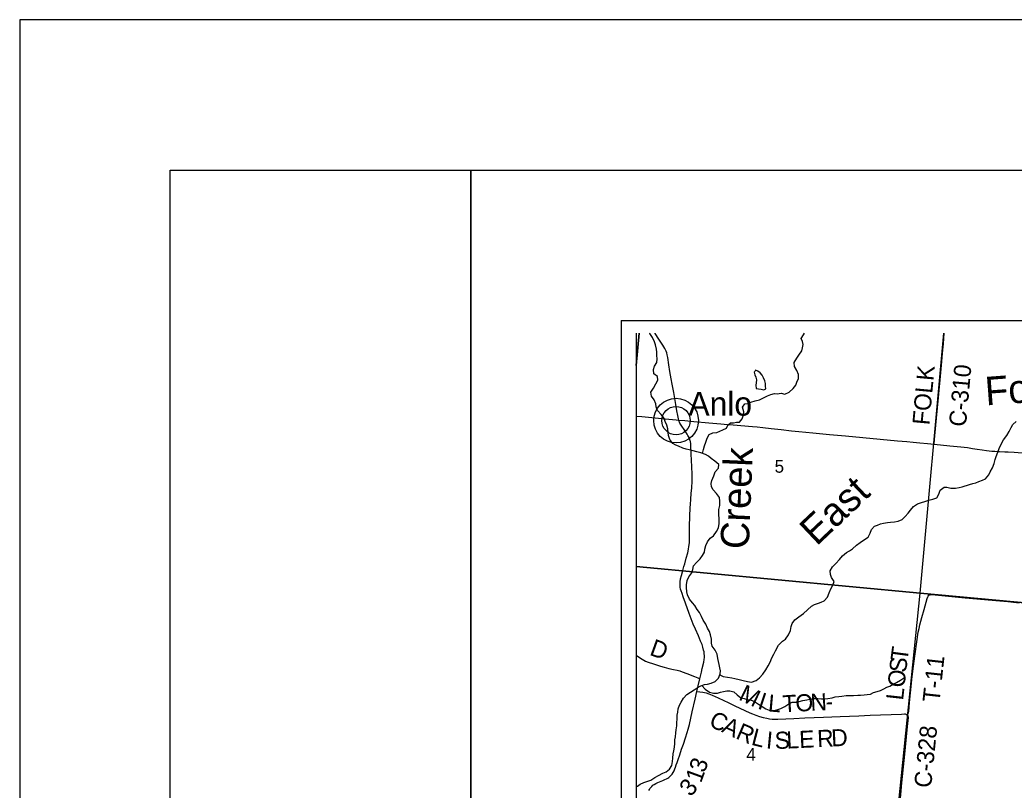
# Model space of a CAD drawing. Extents: x 0 to 34, y 0 to 22.
# Drawn here: x 0 to 3.306, y 19.439 to 22 of the extents above; entities that cross this region are included whole.
import ezdxf

# ---------------------------------------------------------------- set-up
doc = ezdxf.new("R2010")
doc.units = 0
for name, color, linetype in [('GM_X_Corporation', 7, 'Continuous'), ('GM_X_County_Road', 7, 'Continuous'), ('GM_X_County_Road_Text', 7, 'Continuous'), ('GM_X_Minor_Lake', 7, 'Continuous'), ('GM_X_Minor_River', 7, 'Continuous'), ('GM_X_Minor_River_Text', 7, 'Continuous'), ('GM_X_Section_Text', 7, 'Continuous'), ('GM_X_Township_Road', 7, 'Continuous'), ('GM_X_Township_Road_Text', 7, 'Continuous'), ('GM_X_Unincorporated', 7, 'Continuous'), ('GM_X_Unincorporated_Location', 7, 'Continuous'), ('GM_X_Unincorporated_Text', 7, 'Continuous'), ('SH_Border', 7, 'Continuous'), ('SH_Cut_Line', 7, 'Continuous'), ('SH_Data', 7, 'Continuous')]:
    doc.layers.add(name, color=color, linetype=linetype)

msp = doc.modelspace()

# ---------------------------------------------------------------- linework, layer by layer
at = {"layer": 'GM_X_Corporation'}
msp.add_line((2.0494, 20.9578), (2.0494, 17.7739), dxfattribs=at)
for points in [[(2.0494, 20.9578), (2.0494, 20.8508), (2.0598, 20.9578)], [(2.0598, 20.9578), (2.0494, 20.8508), (2.0494, 20.1825), (2.9941, 20.0934), (3.0731, 20.9578)], [(4.0205, 20.9578), (3.9531, 20.0055), (2.9941, 20.0934), (3.0731, 20.9578)]]:
    msp.add_lwpolyline(points, dxfattribs=at)
for points in [[(2.0494, 20.1825), (2.0494, 19.1379), (2.8892, 19.065), (2.9941, 20.0934)], [(2.9941, 20.0934), (3.9531, 20.0055), (3.9103, 18.9545), (2.8892, 19.065)]]:
    msp.add_lwpolyline(points, close=True, dxfattribs=at)
at = {"layer": 'GM_X_County_Road'}
for points in [[(2.1912, 20.6692), (2.1903, 20.6731), (2.188, 20.6847), (2.1853, 20.7), (2.1817, 20.7214), (2.1745, 20.7611), (2.1692, 20.7885), (2.1661, 20.8069), (2.162, 20.8312), (2.1586, 20.8528), (2.1549, 20.8769), (2.154, 20.8816), (2.1528, 20.8866), (2.1511, 20.8926), (2.149, 20.8985), (2.145, 20.9067), (2.138, 20.9178), (2.1252, 20.9384), (2.1132, 20.957), (2.1127, 20.9578)], [(3.0411, 20.589), (3.0422, 20.6048), (3.0486, 20.6759), (3.055, 20.7438), (3.0572, 20.7686), (3.0603, 20.8025), (3.0659, 20.8644), (3.0684, 20.8922), (3.0713, 20.9231), (3.0743, 20.9578)], [(2.0494, 20.6826), (2.0683, 20.6808), (2.1459, 20.6735), (2.183, 20.67), (2.1912, 20.6692)], [(2.2617, 19.8092), (2.2669, 19.8311), (2.2694, 19.843), (2.2741, 19.8643), (2.2759, 19.8735), (2.2765, 19.8797), (2.2766, 19.886), (2.2762, 19.8923), (2.2753, 19.8985), (2.274, 19.9046), (2.2715, 19.9137), (2.2685, 19.9225), (2.264, 19.9341), (2.2567, 19.9513), (2.2464, 19.9739), (2.239, 19.991), (2.2289, 20.0169), (2.2255, 20.0255), (2.2135, 20.0599), (2.2059, 20.0809), (2.2022, 20.0923), (2.1991, 20.1011), (2.1974, 20.1073), (2.1964, 20.1134), (2.1957, 20.1196), (2.1956, 20.1254), (2.196, 20.1317), (2.1972, 20.141), (2.1999, 20.1529), (2.2032, 20.1649), (2.2056, 20.1733), (2.2083, 20.1825), (2.2111, 20.1914), (2.2162, 20.2096), (2.2211, 20.2273), (2.2238, 20.2395), (2.2252, 20.2487), (2.2264, 20.2612), (2.2269, 20.2736), (2.227, 20.2923), (2.2271, 20.3233), (2.2275, 20.3419), (2.2278, 20.3481), (2.2282, 20.3573), (2.2286, 20.3696), (2.2291, 20.3789), (2.2299, 20.3882), (2.2313, 20.4065), (2.2329, 20.4253), (2.2344, 20.4439), (2.2357, 20.4656), (2.2361, 20.478), (2.2359, 20.4905), (2.2349, 20.5122), (2.2335, 20.5368), (2.2326, 20.5553), (2.2315, 20.5832), (2.2314, 20.5863), (2.2311, 20.5892), (2.2308, 20.5919), (2.2303, 20.5948), (2.2297, 20.5977), (2.2291, 20.6005), (2.2283, 20.6037), (2.2272, 20.6068), (2.2253, 20.6112), (2.2219, 20.6175), (2.2191, 20.6226), (2.2137, 20.631), (2.1967, 20.6561), (2.195, 20.6591), (2.1936, 20.6618), (2.1927, 20.664), (2.1916, 20.6672), (2.1912, 20.6692)], [(2.1912, 20.6692), (2.2109, 20.6673), (2.2418, 20.6644), (2.2913, 20.66), (2.3315, 20.6563), (2.3532, 20.6545), (2.3717, 20.6531), (2.4365, 20.6476), (2.452, 20.6462), (2.4705, 20.6443), (2.4982, 20.641), (2.5322, 20.6376), (2.5662, 20.634), (2.5909, 20.6315), (2.6373, 20.627), (2.693, 20.6216), (2.7455, 20.6167), (2.9187, 20.6006), (2.9497, 20.5977), (2.9713, 20.5957), (2.9929, 20.5937), (3.018, 20.5914), (3.0411, 20.589)], [(3.0411, 20.589), (3.0931, 20.5837), (3.1289, 20.5802), (3.1511, 20.5777), (3.1686, 20.5752), (3.1831, 20.5729), (3.2001, 20.57), (3.2141, 20.5682), (3.2323, 20.5663), (3.2418, 20.5655), (3.2515, 20.5649), (3.2578, 20.5646), (3.2761, 20.5637), (3.2871, 20.5632), (3.3064, 20.5623), (3.3328, 20.5606)], [(2.0494, 19.8876), (2.057, 19.8822), (2.07, 19.8737), (2.0754, 19.8707), (2.0811, 19.868), (2.0899, 19.8647), (2.1075, 19.8586), (2.131, 19.8507), (2.143, 19.8472), (2.1581, 19.8435), (2.1733, 19.8403), (2.1854, 19.8377), (2.1943, 19.8352), (2.203, 19.8322), (2.2175, 19.8267), (2.2433, 19.8161), (2.2549, 19.8117), (2.2617, 19.8092)], [(2.2517, 19.7671), (2.256, 19.7857), (2.2617, 19.8092)], [(2.0921, 19.4378), (2.0936, 19.441), (2.0952, 19.4436), (2.0969, 19.4462), (2.0989, 19.4486), (2.1011, 19.4509), (2.1054, 19.4547), (2.1089, 19.457), (2.1154, 19.4607), (2.1213, 19.4637), (2.1386, 19.4709), (2.1444, 19.4736), (2.1502, 19.4763), (2.1547, 19.4788), (2.1579, 19.4811), (2.1623, 19.4846), (2.1659, 19.4881), (2.1692, 19.4919), (2.1727, 19.4973), (2.1755, 19.503), (2.1782, 19.5096), (2.1803, 19.5153), (2.183, 19.5226), (2.1854, 19.5301), (2.1888, 19.54), (2.1946, 19.5565), (2.2007, 19.5744), (2.2066, 19.5918), (2.2136, 19.6122), (2.2194, 19.6298), (2.2229, 19.6416), (2.2267, 19.6566), (2.2362, 19.6989), (2.246, 19.7412), (2.2517, 19.7671)], [(2.2517, 19.7671), (2.2618, 19.7659), (2.2709, 19.7646), (2.2769, 19.7633), (2.2828, 19.7617), (2.2915, 19.7587), (2.3028, 19.754), (2.3225, 19.7451), (2.3416, 19.7362), (2.3555, 19.7298), (2.3779, 19.7192), (2.411, 19.7033), (2.4277, 19.6956), (2.4362, 19.692), (2.4479, 19.6876), (2.4597, 19.6838), (2.4717, 19.6805), (2.4838, 19.6776), (2.4929, 19.6758), (2.5022, 19.6746), (2.5116, 19.6742), (2.5209, 19.6744), (2.5735, 19.6769), (2.6107, 19.6788), (2.6726, 19.6815), (2.7283, 19.6837), (2.7903, 19.6859), (2.8275, 19.6875), (2.9322, 19.6918), (2.9424, 19.6921), (2.9446, 19.6919), (2.9463, 19.6915), (2.948, 19.6907), (2.9494, 19.6899), (2.9516, 19.6883)], [(2.9516, 19.6883), (2.9528, 19.6866), (2.9535, 19.6849), (2.954, 19.6821), (2.9541, 19.6791), (2.9534, 19.6699), (2.9499, 19.6389), (2.9418, 19.5586), (2.9324, 19.4628), (2.9284, 19.4226), (2.9243, 19.3827), (2.9197, 19.334), (2.9161, 19.3), (2.9134, 19.2724), (2.9106, 19.2475)]]:
    msp.add_lwpolyline(points, dxfattribs=at)
at = {"layer": 'GM_X_Minor_Lake'}
for points in [[(2.4437, 20.8312), (2.442, 20.8289), (2.4445, 20.8198), (2.4479, 20.8114), (2.4493, 20.8026), (2.4488, 20.7935), (2.4475, 20.7855), (2.4489, 20.7741)], [(2.4489, 20.7741), (2.4569, 20.7733), (2.4648, 20.7717), (2.4739, 20.7693), (2.4804, 20.773), (2.4798, 20.7821), (2.4799, 20.7909), (2.4773, 20.7996), (2.4733, 20.8092), (2.4685, 20.8184), (2.4621, 20.8268), (2.4546, 20.8322), (2.4466, 20.835), (2.4437, 20.8312)]]:
    msp.add_lwpolyline(points, dxfattribs=at)
at = {"layer": 'GM_X_Minor_River'}
for points in [[(2.227, 20.0741), (2.2207, 20.0886), (2.2181, 20.0981), (2.2164, 20.1122), (2.2165, 20.1217), (2.2186, 20.1354), (2.2252, 20.1475), (2.2349, 20.1614), (2.2377, 20.172), (2.2405, 20.1849), (2.2502, 20.1958), (2.2625, 20.2082), (2.2706, 20.2191), (2.2768, 20.2301), (2.2784, 20.2403), (2.2812, 20.2517), (2.2867, 20.2645), (2.2952, 20.2762), (2.3067, 20.2848), (2.3172, 20.2988), (2.3238, 20.3112), (2.3259, 20.3249), (2.3256, 20.3344), (2.3244, 20.3618), (2.3249, 20.3716), (2.3274, 20.3849), (2.3279, 20.3997), (2.3262, 20.4119), (2.3172, 20.4253), (2.3052, 20.4376), (2.3001, 20.4472), (2.2994, 20.4586), (2.3015, 20.4681), (2.3077, 20.4839), (2.3128, 20.4968), (2.3229, 20.5092), (2.3242, 20.5218), (2.3114, 20.5326), (2.2993, 20.5414), (2.2896, 20.5495), (2.2798, 20.5542), (2.265, 20.5605), (2.251, 20.5633), (2.2389, 20.5669), (2.226, 20.5701), (2.2158, 20.5725), (2.2044, 20.576), (2.1908, 20.5823), (2.181, 20.5858), (2.1712, 20.5916), (2.1615, 20.6043), (2.1567, 20.6176), (2.1565, 20.6279), (2.1547, 20.6397), (2.1515, 20.6523), (2.1463, 20.6649), (2.1415, 20.6771), (2.1322, 20.6879), (2.1202, 20.7009), (2.1162, 20.7135), (2.1148, 20.723), (2.1096, 20.736), (2.1006, 20.7483), (2.0978, 20.7616), (2.1071, 20.7752), (2.1148, 20.7892), (2.1218, 20.802), (2.1205, 20.8142), (2.1084, 20.8235), (2.1071, 20.8379), (2.111, 20.8481), (2.1188, 20.8602), (2.1197, 20.8727), (2.1179, 20.8841), (2.1184, 20.8948), (2.1171, 20.9047), (2.1142, 20.9192), (2.1105, 20.9291), (2.1035, 20.9436), (2.0949, 20.957), (2.0938, 20.9578)], [(2.2699, 20.5584), (2.2731, 20.571), (2.2767, 20.5839), (2.2814, 20.5956), (2.2854, 20.6089), (2.2924, 20.6213), (2.3046, 20.6265), (2.3179, 20.6279), (2.3275, 20.6323), (2.3374, 20.6364), (2.3504, 20.6419), (2.3539, 20.6525), (2.3635, 20.6604), (2.373, 20.6606), (2.3837, 20.662), (2.3936, 20.6619), (2.402, 20.6728), (2.4064, 20.6872), (2.4077, 20.6967), (2.4029, 20.7116), (2.4114, 20.7229), (2.4209, 20.7243), (2.4309, 20.7284), (2.4457, 20.7327), (2.4598, 20.7368), (2.4732, 20.7431), (2.4858, 20.7494), (2.4969, 20.7542), (2.5091, 20.7574), (2.5186, 20.757), (2.5319, 20.7583), (2.544, 20.7555), (2.5585, 20.7618), (2.572, 20.7742), (2.5801, 20.7851), (2.5844, 20.7949), (2.5891, 20.8078), (2.5897, 20.8211), (2.5834, 20.8345), (2.5759, 20.8475), (2.5746, 20.8608), (2.5835, 20.8747), (2.5901, 20.8853), (2.6001, 20.8992), (2.6025, 20.9091), (2.605, 20.9205), (2.6024, 20.9308), (2.598, 20.9407), (2.6065, 20.9524), (2.6095, 20.9578)], [(2.3273, 19.8219), (2.3388, 19.817), (2.3528, 19.8138), (2.3676, 19.8118), (2.3775, 19.8094), (2.3926, 19.8065), (2.4055, 19.8037), (2.4195, 19.7994), (2.4335, 19.7977), (2.4488, 19.8036), (2.4592, 19.8118), (2.4703, 19.8238), (2.4804, 19.8389), (2.4886, 19.8525), (2.4955, 19.8646), (2.501, 19.8782), (2.5069, 19.8906), (2.5131, 19.9016), (2.5232, 19.9212), (2.5363, 19.934), (2.5463, 19.9411), (2.5567, 19.9554), (2.5626, 19.9694), (2.5646, 19.9823), (2.5682, 19.9929), (2.5775, 20.0049), (2.5909, 20.0154), (2.6055, 20.0262), (2.6189, 20.0382), (2.6327, 20.0506), (2.6427, 20.0562), (2.6557, 20.0606), (2.6652, 20.0639), (2.6747, 20.068), (2.6855, 20.0804), (2.6918, 20.0944), (2.6965, 20.108), (2.7039, 20.1204), (2.7082, 20.1329), (2.6997, 20.146), (2.696, 20.1559), (2.6942, 20.1677), (2.7024, 20.1809), (2.7139, 20.1918), (2.7262, 20.2057), (2.7355, 20.2181), (2.7486, 20.229), (2.7585, 20.2342), (2.7692, 20.2413), (2.7819, 20.2529), (2.795, 20.2626), (2.8084, 20.2716), (2.8206, 20.2798), (2.8276, 20.2926), (2.8327, 20.3055), (2.842, 20.3164), (2.8523, 20.3197), (2.8626, 20.3238), (2.8721, 20.3263), (2.8854, 20.3284), (2.8953, 20.3294), (2.909, 20.3304), (2.9208, 20.3326), (2.9346, 20.3385), (2.9446, 20.349), (2.9542, 20.3595), (2.9619, 20.3693), (2.972, 20.3821), (2.9854, 20.3903), (2.9983, 20.3955), (3.0094, 20.3988), (3.0227, 20.4024), (3.0357, 20.406), (3.0494, 20.4112), (3.0564, 20.4233), (3.0608, 20.4358), (3.0734, 20.4466), (3.0829, 20.4461), (3.0962, 20.4429), (3.111, 20.4428), (3.1239, 20.4449), (3.1335, 20.4471), (3.1586, 20.4551), (3.1689, 20.458), (3.1788, 20.4606), (3.1891, 20.465), (3.2017, 20.469), (3.2117, 20.4742), (3.2221, 20.4874), (3.2268, 20.4976), (3.2342, 20.5108), (3.2404, 20.5244), (3.2436, 20.5377), (3.2472, 20.5479), (3.2527, 20.5627), (3.257, 20.5748), (3.2636, 20.5895), (3.2707, 20.6035), (3.2818, 20.6174), (3.29, 20.6314), (3.2966, 20.645)], [(3.2966, 20.645), (3.3021, 20.6548), (3.3132, 20.665)], [(2.0494, 19.4507), (2.0535, 19.4523), (2.0631, 19.4583), (2.0749, 19.4638), (2.0852, 19.4671), (2.0982, 19.4723), (2.1112, 19.4805), (2.1239, 19.4872), (2.1384, 19.4946), (2.1495, 19.4994), (2.1606, 19.5084), (2.168, 19.5205), (2.17, 19.5341), (2.1713, 19.5444), (2.173, 19.5588), (2.175, 19.569), (2.1771, 19.5815), (2.178, 19.5937), (2.1785, 19.6062), (2.1798, 19.6161), (2.1811, 19.6293), (2.1824, 19.6392), (2.1844, 19.6529), (2.1846, 19.6624), (2.1855, 19.6756), (2.1864, 19.6874), (2.1877, 19.6976), (2.1897, 19.7094), (2.1937, 19.7215), (2.1991, 19.7317), (2.2072, 19.7449), (2.218, 19.7562), (2.2307, 19.7644), (2.2429, 19.7722), (2.2525, 19.7786), (2.2647, 19.786), (2.2769, 19.7897), (2.2868, 19.7914), (2.299, 19.7947), (2.3124, 19.7999), (2.3228, 19.8115), (2.3287, 19.8251), (2.3296, 19.8354), (2.3278, 19.8457), (2.326, 19.8563), (2.3231, 19.8659), (2.3213, 19.8761), (2.3185, 19.8906), (2.3126, 19.904), (2.3025, 19.917), (2.3003, 19.9277), (2.3001, 19.941), (2.2965, 19.9555), (2.2932, 19.9665), (2.2873, 19.9772), (2.281, 19.9902), (2.2724, 20.0033), (2.2669, 20.0159), (2.2606, 20.0289), (2.2524, 20.0396), (2.2442, 20.0522), (2.2367, 20.0618), (2.227, 20.0741)], [(2.2678, 19.7869), (2.2794, 19.7748), (2.293, 19.7644), (2.3066, 19.7608), (2.3195, 19.7614), (2.3302, 19.764), (2.3405, 19.7665), (2.3515, 19.7686), (2.3614, 19.7693), (2.3743, 19.7657), (2.3852, 19.7553), (2.3972, 19.7457), (2.4085, 19.7429), (2.4195, 19.7405), (2.4294, 19.7384), (2.443, 19.7337), (2.4566, 19.7248), (2.4686, 19.7167), (2.4811, 19.709), (2.4913, 19.705), (2.5019, 19.7034), (2.5114, 19.7048), (2.5209, 19.7073), (2.5305, 19.7103), (2.5442, 19.7162), (2.5538, 19.7229), (2.5683, 19.7307), (2.582, 19.7313), (2.5915, 19.7331), (2.6041, 19.7367), (2.6167, 19.7389), (2.6266, 19.7414), (2.6403, 19.7435), (2.6536, 19.743), (2.6661, 19.7417), (2.6767, 19.7419), (2.6874, 19.7429), (2.7011, 19.7454), (2.7117, 19.7484), (2.7235, 19.7501), (2.7338, 19.7507), (2.7479, 19.7529), (2.7627, 19.7538), (2.7726, 19.7537), (2.7863, 19.7539), (2.7958, 19.7546), (2.8083, 19.7555), (2.8182, 19.7566), (2.8285, 19.7583), (2.8384, 19.7632), (2.851, 19.7668), (2.8617, 19.7705), (2.8728, 19.7753), (2.8831, 19.7805), (2.8926, 19.7849), (2.906, 19.7916), (2.9156, 19.7964), (2.929, 19.8046), (2.9424, 19.8132)]]:
    msp.add_lwpolyline(points, dxfattribs=at)
at = {"layer": 'GM_X_Township_Road'}
msp.add_lwpolyline([(2.9516, 19.6883), (2.9533, 19.6908), (2.9545, 19.6933), (2.9552, 19.6959), (2.9558, 19.6999), (2.9587, 19.7303), (2.9637, 19.7828), (2.9676, 19.8167), (2.9715, 19.8506), (2.9762, 19.8844), (2.9839, 19.9398), (2.9878, 19.9643), (2.9902, 19.9765), (2.9932, 19.9886), (3.0001, 20.0124), (3.0076, 20.0393), (3.0109, 20.0513), (3.0173, 20.0754), (3.0193, 20.0813), (3.0209, 20.0842), (3.0232, 20.0866), (3.0261, 20.0883), (3.0272, 20.0886), (3.0293, 20.089), (3.0325, 20.0891), (3.0882, 20.0835), (3.1438, 20.0785), (3.2458, 20.0694), (3.2859, 20.0654), (3.323, 20.0617)], dxfattribs=at)
at = {"layer": 'GM_X_Unincorporated'}
for radius in [0.0744, 0.0472]:
    msp.add_circle((2.1822, 20.6674), radius, dxfattribs=at)
at = {"layer": 'GM_X_Unincorporated_Location'}
msp.add_line((2.1822, 20.6674), (2.1822, 20.6674), dxfattribs=at)
at = {"layer": 'SH_Border'}
for points in [[(0.5, 21.5), (1.5, 21.5), (1.5, 0.5), (0.5, 0.5)], [(1.5, 21.5), (33.5, 21.5), (33.5, 0.5), (1.5, 0.5)]]:
    msp.add_lwpolyline(points, close=True, dxfattribs=at)
at = {"layer": 'SH_Cut_Line'}
msp.add_lwpolyline([(0, 0), (34, 0), (34, 22), (0, 22)], close=True, dxfattribs=at)
at = {"layer": 'SH_Data'}
for q in [(9, 21), (2, 17.5)]:
    msp.add_line((2, 21), q, dxfattribs=at)

# ---------------------------------------------------------------- texts
at = {"layer": 'GM_X_County_Road_Text'}
for s, height, rotation, p in [('FOLK', 0.05682, 84.782, (3.0245, 20.6511)), ('C-310', 0.05682, 84.7823, (3.146, 20.6454)), ('D', 0.0568, 340.127, (2.0912, 19.8892)), ('M', 0.0568, 334.1575, (2.3874, 19.7408)), ('I', 0.0568, 341.9086, (2.4507, 19.7108)), ('L', 0.0568, 355.0031, (2.4867, 19.7007)), ('T', 0.0568, 3.4558, (2.5382, 19.6969)), ('O', 0.0568, 2.901, (2.5805, 19.6994)), ('N', 0.0568, 2.8971, (2.6304, 19.702)), ('-', 0.0568, 2.9001, (2.6804, 19.7045)), ('C', 0.0568, 335.0305, (2.288, 19.6531)), ('A', 0.0568, 335.2699, (2.3306, 19.6332)), ('R', 0.0568, 336.7949, (2.3775, 19.6117)), ('L', 0.0568, 345.6058, (2.4294, 19.5902)), ('D', 0.0568, 2.6909, (2.6995, 19.5836)), ('C-328', 0.05682, 84.226, (3.0302, 19.4444)), ('I', 0.0568, 354.5179, (2.4801, 19.578)), ('S', 0.0568, 1.6683, (2.511, 19.5755)), ('L', 0.0568, 2.6329, (2.5504, 19.5766)), ('E', 0.0568, 2.6796, (2.5929, 19.5786)), ('R', 0.0568, 2.6903, (2.6528, 19.5814)), ('3', 0.0568, 70.5976, (2.2772, 19.4936)), ('1', 0.0568, 70.0619, (2.2651, 19.4601)), ('3', 0.0568, 48.968, (2.2305, 19.4142))]:
    msp.add_text(s, height=height, rotation=rotation, dxfattribs=at).set_placement(p)
at = {"layer": 'GM_X_Minor_River_Text'}
for s, height, rotation, p in [('Fork', 0.0947, 4.283, (3.213, 20.7178)), ('Creek', 0.09476, 87.6381, (2.424, 20.2387)), ('East', 0.09473, 43.428, (2.6492, 20.2481))]:
    msp.add_text(s, height=height, rotation=rotation, dxfattribs=at).set_placement(p)
at = {"layer": 'GM_X_Section_Text'}
for s, p in [('5', (2.5101, 20.4942)), ('4', (2.416, 19.5365))]:
    msp.add_text(s, height=0.0419, rotation=0, dxfattribs=at).set_placement(p)
at = {"layer": 'GM_X_Township_Road_Text'}
for s, height, rotation, p in [('T', 0.0568, 82.4917, (2.9514, 19.8654)), ('S', 0.0568, 83.6341, (2.9472, 19.8276)), ('T-11', 0.05682, 83.7459, (3.0582, 19.7287)), ('O', 0.0568, 83.7294, (2.9417, 19.7779)), ('L', 0.0568, 83.7303, (2.9371, 19.7356))]:
    msp.add_text(s, height=height, rotation=rotation, dxfattribs=at).set_placement(p)
at = {"layer": 'GM_X_Unincorporated_Text'}
msp.add_text('Anlo', height=0.07898, rotation=0, dxfattribs=at).set_placement((2.2235, 20.684))

doc.saveas('drawing.dxf')
